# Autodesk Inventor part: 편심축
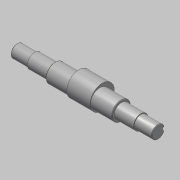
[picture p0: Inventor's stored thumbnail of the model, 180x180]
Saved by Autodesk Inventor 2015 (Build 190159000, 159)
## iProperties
Created: 2015-10
Part Number: 편심축
Document SubType Name: Modeling
Designer: mdu
Density: 1 g/cm^3
Material: 강철, 연강
Mass: 168.947 g
Surface Area: 248.524 cm^2
Volume: 168.947 cm^3
Appearance: 강철
Author: mdu
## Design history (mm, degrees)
sketch "스케치1"
  geometry: L1 (-20.5, -41.331)-(-20.5, 32.669) reference; L2 (7.5, -30.031)-(7.5, 21.369) reference; L3 (135.5, -30.331)-(135.5, 21.669) reference; L4 (121.5, 21.369)-(121.5, -30.031) reference; L5 (184.5, -4.331)-(-57.5, -4.331); L6 (184.5, -4.331)-(184.5, 6.669); L7 (154.5, 8.169)-(121.5, 8.169); L8 (121.5, 8.169)-(121.5, 11.669); L9 (121.5, 11.669)-(7.5, 11.669); L10 (7.5, 11.669)-(7.5, 8.169); L11 (7.5, 8.169)-(-27.5, 8.169); L12 (-27.5, 8.169)-(-27.5, 6.669); L13 (-27.5, 6.669)-(-57.5, 6.669); L14 (-57.5, 6.669)-(-57.5, -4.331); L15 (154.5, 8.169)-(154.5, 6.669); L16 (154.5, 6.669)-(184.5, 6.669); C1 r 32.5 at (64.5, -4.331) reference; 1 further point
  constraints: 24 end point, 8 perpendicular, 5 point on line, 3 parallel, 2 collinear
  dimensions: "d1" = 25 diameter of L11 L5; "d2" = 32 diameter of L9 L5; "d3" = 22 diameter of L13 L5; "d4" = 35 distance of L10.end L11.end; "d5" = 30 distance of L12.end L13.end; "d15" = 33 distance of L7.start L7.end; "d26" = 30 distance of L15.end L6.end
revolve "회전1" sketch "스케치1" stored, may be unused: angle "d6" = 90 deg
node "작업 평면1"
sketch "스케치2"
  geometry: C1 r 16 at (0, 0) reference; C2 r 20.75 at (0, 4)
  constraints: 1 centre point, 1 vertical alignment
  dimensions: "d34" = 4 distance of C2.centre C1.centre; "d35" = 41.5 diameter of C2
extrude "돌출1" join sketch "스케치2" stored distance "d9" = 40; taper "d10" = 0 deg
chamfer "모따기1" distance "d11" = 1; stored, may be unused: second distance "d12" = 2, angle "d13" = 45 deg
node "작업 평면2"
sketch "스케치3"
  geometry: L1 (-15, -10)-(-15, 10) reference; L2 (-15, 3)-(0, 3); L3 (0, -3)-(-15, -3); A1 r 3 centre (0, 0) between (0, -3) and (0, 3); 2 further points
  constraints: 4 end point, 2 perpendicular, 2 point on circle, 2 point on line, 2 tangent, 1 centre point, 1 horizontal alignment, 1 midpoint
  dimensions: "d16" = 18 dimension on A1 L1; "d17" = 6 distance between parallel lines of L3 L2
extrude "돌출2" cut sketch "스케치3" distance "d18" = 3.5; taper "d19" = 0 deg
node "작업 평면3"
node "솔리드1"
mirror "대칭1"
node "참조1"
node "참조2"
node "참조3"
node "참조4"
node "참조5"
other parameters: "d30" = 35
